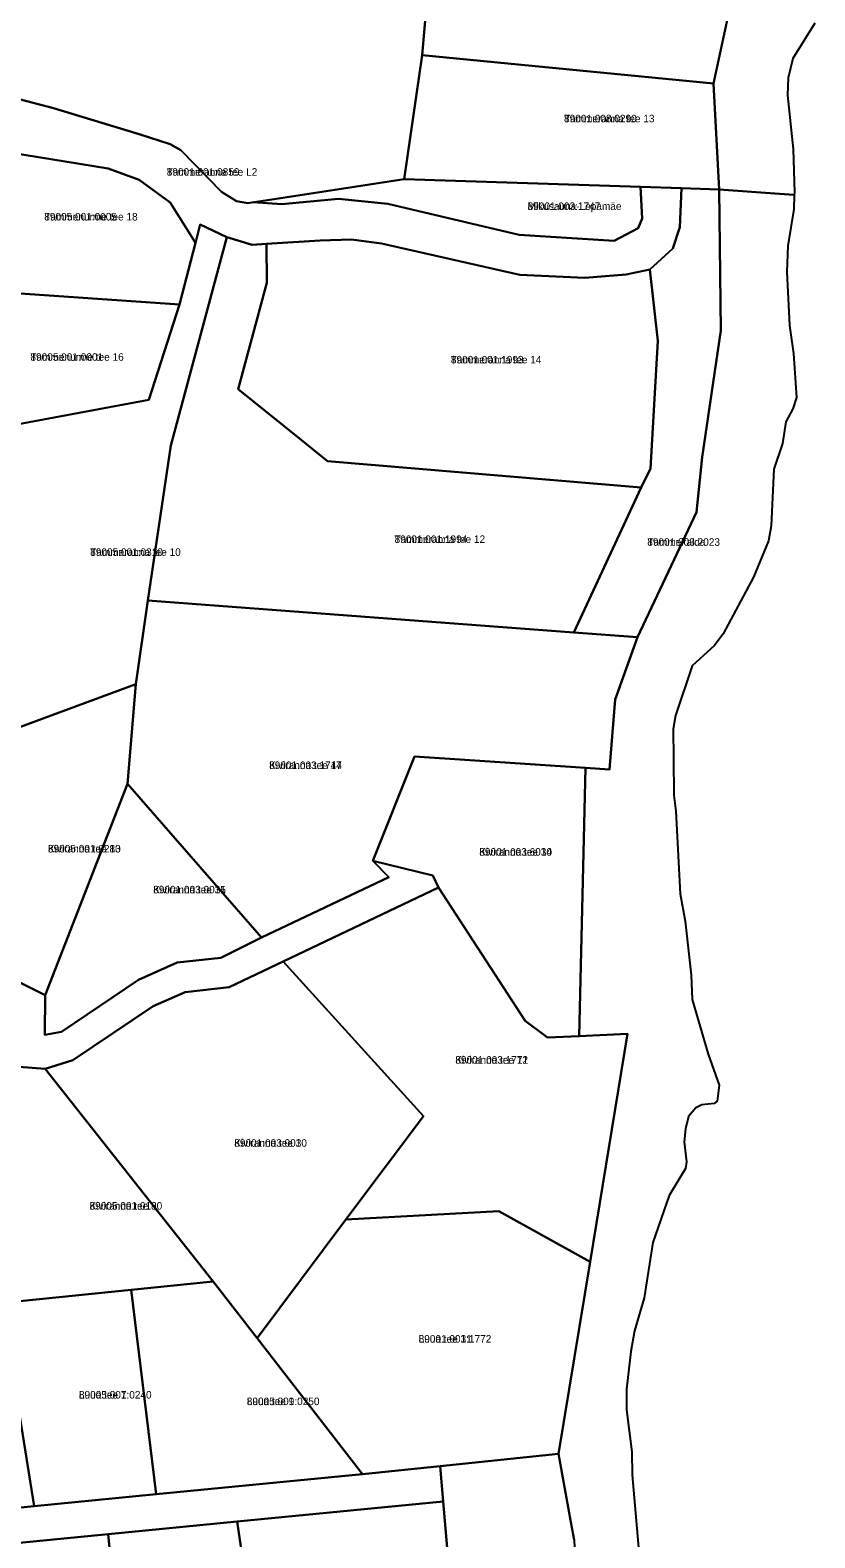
# Model space of a CAD drawing. Extents: x 526849 to 562296, y 6591741 to 6618546.
# Drawn here: x 551536.1 to 551692.6, y 6598005.8 to 6598306.4 of the extents above; entities that cross this region are included whole.
import ezdxf

# ---------------------------------------------------------------- set-up
doc = ezdxf.new("R2010")
doc.units = 0
for name, color, linetype in [('L_AADRESS', 7, 'Continuous'), ('PIIR', 7, 'Continuous'), ('TUNNUS', 7, 'Continuous')]:
    doc.layers.add(name, color=color, linetype=linetype)

msp = doc.modelspace()

# ---------------------------------------------------------------- linework, layer by layer
at = {"layer": 'PIIR'}
for points in [[(551616.38, 6598325.88), (551614.28, 6598301.43), (551610.71, 6598276.69), (551584.71, 6598272.74), (551579.47, 6598271.94), (551577.2, 6598272.32), (551574.25, 6598274.17), (551566.13, 6598282.47), (551563.97, 6598283.71), (551557.84, 6598285.69), (551540.69, 6598290.86), (551532.58, 6598292.98), (551506.46, 6598296.92), (551495.19, 6598297.22), (551477.49, 6598297.73), (551466.09, 6598296.84), (551469.66, 6598302.38), (551473.44, 6598308.11)], [(551692.62, 6598307.8), (551688.23, 6598300.76), (551687.31, 6598296.93), (551687.19, 6598293.43), (551688.28, 6598282.66), (551688.53, 6598274.02), (551688.51, 6598273.57), (551685.58, 6598273.78), (551673.5, 6598274.64), (551672.38, 6598295.77), (551678.27, 6598322.92)], [(551532.58, 6598292.98), (551540.69, 6598290.86), (551557.84, 6598285.69), (551563.97, 6598283.71), (551566.13, 6598282.47), (551574.25, 6598274.17), (551577.2, 6598272.32), (551579.47, 6598271.94), (551580.57, 6598272.11), (551586.24, 6598271.71), (551597.59, 6598272.75), (551607.4, 6598271.77), (551633.61, 6598265.61), (551652.6, 6598264.43), (551657.38, 6598266.92), (551658.15, 6598268.84), (551657.86, 6598275.15), (551665.99, 6598274.89), (551665.69, 6598267.12), (551664.26, 6598262.85), (551659.71, 6598258.66), (551654.99, 6598257.68), (551646.75, 6598257.05), (551633.73, 6598257.61), (551606.13, 6598263.85), (551600.2, 6598264.69), (551593.95, 6598264.5), (551583.24, 6598263.78), (551580.34, 6598263.61), (551575.28, 6598265.13), (551569.97, 6598267.65), (551569.02, 6598263.98), (551563.99, 6598272.06), (551557.81, 6598276.54), (551551.65, 6598278.82), (551512.29, 6598285.23)], [(551644.59, 6598005.37), (551644.15, 6598007.88), (551641.46, 6598022.51), (551647.76, 6598060.83), (551655.23, 6598106.26), (551645.61, 6598105.84), (551646.88, 6598159.31), (551651.68, 6598159), (551652.78, 6598172.98), (551657.26, 6598185.41), (551669, 6598210.32), (551670.16, 6598221.25), (551673.85, 6598246.55), (551673.5, 6598274.64), (551685.58, 6598273.78), (551688.51, 6598273.57), (551688.41, 6598270.75), (551687.21, 6598263.4), (551687.04, 6598258.22), (551687.54, 6598247.52), (551688.39, 6598241.95), (551688.96, 6598233.16), (551688.2, 6598230.92), (551686.8, 6598228.29), (551686.17, 6598224.01), (551684.45, 6598218.86), (551683.91, 6598207.6), (551683.34, 6598204.57), (551680.4, 6598197.33), (551674.33, 6598186.06), (551672.61, 6598183.72), (551668.15, 6598179.63), (551664.81, 6598169.79), (551664.34, 6598167.01), (551664.41, 6598161.19), (551664.5, 6598153.84), (551664.89, 6598150.69), (551665.75, 6598134.17), (551666.72, 6598128.76), (551667.91, 6598117.96), (551668.15, 6598113.12), (551671.32, 6598102.24), (551673.54, 6598096.05), (551673.15, 6598092.88), (551672.51, 6598092.4), (551670.09, 6598092.12), (551668.9, 6598091.56), (551667.41, 6598089.83), (551666.78, 6598087.31), (551666.57, 6598084.75), (551667.04, 6598080.73), (551666.8, 6598079.46), (551663.54, 6598074.07), (551660.29, 6598064.7), (551658.54, 6598053.67), (551656.66, 6598047.04), (551655.88, 6598042.95), (551655.05, 6598035.41), (551655.05, 6598031.28), (551656.08, 6598022.95), (551656.16, 6598018.34), (551658.3, 6597993.9)], [(551527.77, 6598119.58), (551539.06, 6598113.96), (551539.02, 6598106.1), (551542.28, 6598106.69), (551557.69, 6598117.03), (551565.36, 6598120.48), (551574.07, 6598121.43), (551582.2, 6598125.52), (551607.63, 6598137.55), (551604.46, 6598140.77), (551616.42, 6598137.85), (551617.5, 6598135.43), (551586.56, 6598120.71), (551575.79, 6598115.59), (551566.96, 6598114.62), (551560.61, 6598111.77), (551544.58, 6598101.01), (551539.04, 6598099.29), (551523.26, 6598100.49)]]:
    msp.add_lwpolyline(points, dxfattribs=at)
for points in [[(551672.38, 6598295.77), (551614.28, 6598301.43), (551616.38, 6598325.88), (551678.27, 6598322.92)], [(551673.5, 6598274.64), (551665.99, 6598274.89), (551657.86, 6598275.15), (551610.71, 6598276.69), (551614.28, 6598301.43), (551672.38, 6598295.77)], [(551512.29, 6598285.23), (551551.65, 6598278.82), (551557.81, 6598276.54), (551563.99, 6598272.06), (551569.02, 6598263.98), (551565.85, 6598251.68), (551510.93, 6598255.53)], [(551580.57, 6598272.11), (551584.71, 6598272.74), (551610.71, 6598276.69), (551657.86, 6598275.15), (551658.15, 6598268.84), (551657.38, 6598266.92), (551652.6, 6598264.43), (551633.61, 6598265.61), (551607.4, 6598271.77), (551597.59, 6598272.75), (551586.24, 6598271.71)], [(551659.71, 6598258.66), (551664.26, 6598262.85), (551665.69, 6598267.12), (551665.99, 6598274.89), (551673.5, 6598274.64), (551673.85, 6598246.55), (551670.16, 6598221.25), (551669, 6598210.32), (551657.26, 6598185.41), (551644.52, 6598186.33), (551657.99, 6598215.22), (551659.82, 6598219.03), (551661.3, 6598244.47)], [(551569.97, 6598267.65), (551575.28, 6598265.13), (551564.12, 6598223.59), (551559.54, 6598192.66), (551557.17, 6598176.02), (551533.57, 6598167.28), (551532.38, 6598198.05), (551526.14, 6598212.02), (551520.8, 6598225.45), (551559.75, 6598232.72), (551565.85, 6598251.68), (551569.02, 6598263.98)], [(551657.99, 6598215.22), (551644.52, 6598186.33), (551559.54, 6598192.66), (551564.12, 6598223.59), (551575.28, 6598265.14), (551580.34, 6598263.61), (551583.24, 6598263.78), (551583.28, 6598256), (551577.59, 6598234.85), (551589.78, 6598224.97), (551595.39, 6598220.44)], [(551583.28, 6598256), (551583.24, 6598263.78), (551593.95, 6598264.5), (551600.2, 6598264.69), (551606.13, 6598263.85), (551633.73, 6598257.61), (551646.75, 6598257.05), (551654.99, 6598257.68), (551659.71, 6598258.66), (551661.3, 6598244.47), (551659.82, 6598219.03), (551657.99, 6598215.22), (551595.39, 6598220.44), (551589.78, 6598224.97), (551577.59, 6598234.85)], [(551510.93, 6598255.53), (551565.85, 6598251.68), (551559.75, 6598232.72), (551520.8, 6598225.45), (551510.56, 6598239.08), (551505.62, 6598250.97)], [(551559.54, 6598192.66), (551644.52, 6598186.33), (551657.26, 6598185.41), (551652.78, 6598172.98), (551651.68, 6598159), (551646.88, 6598159.31), (551612.72, 6598161.55), (551604.46, 6598140.77), (551607.63, 6598137.55), (551582.2, 6598125.52), (551555.49, 6598156.1), (551557.17, 6598176.02)], [(551555.49, 6598156.1), (551539.06, 6598113.96), (551527.77, 6598119.58), (551522.06, 6598127.92), (551533.57, 6598167.28), (551557.17, 6598176.02)], [(551604.46, 6598140.77), (551612.72, 6598161.55), (551646.88, 6598159.31), (551645.61, 6598105.84), (551639.28, 6598105.57), (551634.83, 6598108.88), (551617.5, 6598135.43), (551616.42, 6598137.85)], [(551555.49, 6598156.1), (551582.2, 6598125.52), (551574.07, 6598121.43), (551565.36, 6598120.48), (551557.69, 6598117.03), (551542.28, 6598106.69), (551539.02, 6598106.1), (551539.06, 6598113.96)], [(551586.56, 6598120.71), (551617.5, 6598135.43), (551634.83, 6598108.88), (551639.28, 6598105.57), (551645.61, 6598105.84), (551655.23, 6598106.26), (551647.76, 6598060.83), (551629.56, 6598070.91), (551599.06, 6598069.25), (551614.52, 6598089.88)], [(551539.04, 6598099.29), (551544.58, 6598101.01), (551560.61, 6598111.77), (551566.96, 6598114.62), (551575.79, 6598115.59), (551586.56, 6598120.71), (551614.52, 6598089.88), (551599.06, 6598069.25), (551581.34, 6598045.6), (551572.57, 6598056.9)], [(551523.26, 6598100.49), (551539.04, 6598099.29), (551572.57, 6598056.9), (551556.18, 6598055.22), (551533.98, 6598052.97)], [(551599.06, 6598069.25), (551629.56, 6598070.91), (551647.76, 6598060.83), (551641.46, 6598022.51), (551617.86, 6598020.09), (551602.38, 6598018.5), (551581.34, 6598045.6)], [(551572.57, 6598056.9), (551581.34, 6598045.6), (551602.38, 6598018.5), (551561.17, 6598014.48), (551556.18, 6598055.22)], [(551561.17, 6598014.48), (551536.84, 6598012.08), (551530.41, 6598052.44), (551533.98, 6598052.97), (551556.18, 6598055.22)], [(551536.84, 6598012.08), (551511.34, 6598009.59), (551506.22, 6598049.61), (551510.48, 6598050.09), (551530.41, 6598052.44)], [(551485.5, 6598008.09), (551511.34, 6598009.59), (551536.84, 6598012.08), (551561.17, 6598014.48), (551602.38, 6598018.5), (551617.86, 6598020.09), (551618.46, 6598013.03), (551577.33, 6598009.02), (551551.65, 6598006.5), (551528.39, 6598004.23), (551503.17, 6598002.03), (551478.25, 6598001.21), (551450.49, 6597999.32), (551446.99, 6597994.51), (551443.72, 6598005.99), (551446.75, 6598006.13)], [(551617.86, 6598020.09), (551641.46, 6598022.51), (551644.15, 6598007.88), (551644.59, 6598005.37), (551644.95, 6597997.5), (551644.67, 6597994.64), (551639.56, 6597974.03), (551640.3, 6597956.86), (551640.24, 6597955.25), (551638.99, 6597944.7), (551636.37, 6597939.05), (551633.87, 6597936.37), (551632.7, 6597935.3), (551629.48, 6597932.79), (551625.6, 6597929.78), (551625.19, 6597934.56), (551624.69, 6597940.3), (551621.56, 6597976.84), (551618.46, 6598013.03)], [(551618.46, 6598013.03), (551621.56, 6597976.84), (551582.72, 6597972.25), (551577.33, 6598009.02)], [(551551.65, 6598006.5), (551577.33, 6598009.02), (551582.72, 6597972.25), (551578.64, 6597971.77), (551555.29, 6597969.57)], [(551551.65, 6598006.5), (551555.29, 6597969.57), (551552.79, 6597968.88), (551529.27, 6597965.9), (551528.39, 6598004.23)]]:
    msp.add_lwpolyline(points, close=True, dxfattribs=at)

# ---------------------------------------------------------------- texts
at = {"layer": 'L_AADRESS'}
for s, p in [('Tammeranna tee 13', (551642.57, 6598288.04)), ('Tammeranna tee L2', (551563.31, 6598277.39)), ('Tammenurme tee 18', (551538.88, 6598268.46)), ('Mikusauna-Lepamäe', (551635.31, 6598270.56)), ('Tammenurme tee 16', (551536.11, 6598240.49)), ('Tammeranna tee 14', (551620, 6598239.96)), ('Tammeranna tee 12', (551608.77, 6598204.16)), ('Tammekalda', (551659.19, 6598203.6)), ('Tammeranna tee 10', (551548.04, 6598201.59)), ('Kiviranna tee 17', (551583.74, 6598159.09)), ('Kiviranna tee 13', (551539.62, 6598142.45)), ('Kiviranna tee 14', (551625.67, 6598141.81)), ('Kiviranna tee 15', (551560.61, 6598134.29)), ('Kiviranna tee 12', (551620.89, 6598100.33)), ('Kiviranna tee 10', (551576.78, 6598083.77)), ('Kiviranna tee 8', (551547.91, 6598071.23)), ('Luua tee 11', (551613.57, 6598044.71)), ('Luua tee 7', (551545.79, 6598033.56)), ('Luua tee 9', (551579.28, 6598032.25))]:
    msp.add_text(s, height=1.5, dxfattribs=at).set_placement(p)
at = {"layer": 'TUNNUS'}
for s, p in [('89001:008:0290', (551642.57, 6598288.04)), ('89001:001:0859', (551563.31, 6598277.39)), ('89005:001:0005', (551538.88, 6598268.46)), ('89001:003:1747', (551635.31, 6598270.56)), ('89005:001:0001', (551536.11, 6598240.49)), ('89001:001:1993', (551620, 6598239.96)), ('89001:001:1994', (551608.77, 6598204.16)), ('89001:003:2023', (551659.19, 6598203.6)), ('89005:001:0310', (551548.04, 6598201.59)), ('89001:003:1744', (551583.74, 6598159.09)), ('89005:001:0280', (551539.62, 6598142.45)), ('89001:003:6030', (551625.67, 6598141.81)), ('89001:003:0031', (551560.61, 6598134.29)), ('89001:003:1771', (551620.89, 6598100.33)), ('89001:003:0030', (551576.78, 6598083.77)), ('89005:001:0190', (551547.91, 6598071.23)), ('89001:003:1772', (551613.57, 6598044.71)), ('89005:001:0240', (551545.79, 6598033.56)), ('89005:001:0250', (551579.28, 6598032.25))]:
    msp.add_text(s, height=1.5, dxfattribs=at).set_placement(p)

doc.saveas('drawing.dxf')
